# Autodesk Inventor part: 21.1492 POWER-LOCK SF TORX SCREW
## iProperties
Created: 2009-01
Part Number: 21.1492 POWER-LOCK SF TORX SCREW
Document SubType Name: Modeling
Designer: Administrator
Density: 7.86 g/cm^3
Material: Steel, Mild
Mass: 11.0398 g
Surface Area: 13.2193 cm^2
Volume: 1.40456 cm^3
Author: Administrator
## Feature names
1. Base1
